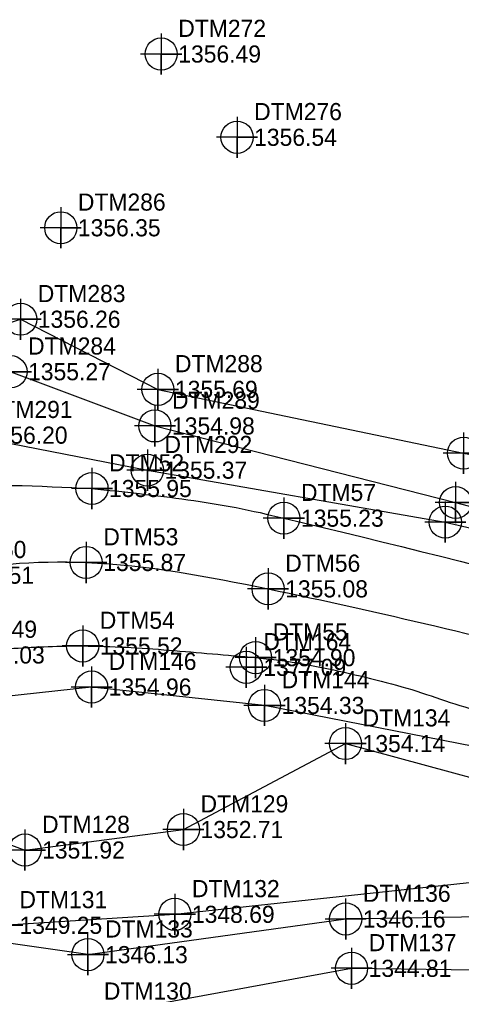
# Model space of a CAD drawing. Extents: x 1251905 to 1252853, y 859795 to 860170.
# Drawn here: x 1252087.6 to 1252152.2, y 860021.6 to 860163.9 of the extents above; entities that cross this region are included whole.
import ezdxf

# ---------------------------------------------------------------- set-up
doc = ezdxf.new("R2010")
doc.units = 0
for name, color, linetype in [('Exist DTM Breakline', 7, 'Continuous'), ('Exist DTM Breakline Cogo Elevation', 7, 'Continuous'), ('Exist DTM Breakline Cogo Number', 7, 'Continuous'), ('Exist DTM Breakline Cogo Point CELL', 7, 'Continuous'), ('Exist DTM Breakline Underwater', 7, 'Continuous'), ('Exist DTM Breakline Underwater Cogo Elevation', 7, 'Continuous'), ('Exist DTM Breakline Underwater Cogo Number', 7, 'Continuous'), ('Exist DTM Breakline Underwater Cogo Point CELL', 7, 'Continuous'), ('Exist DTM Crownline', 7, 'Continuous'), ('Exist DTM Crownline Cogo Elevation', 7, 'Continuous'), ('Exist DTM Crownline Cogo Number', 7, 'Continuous'), ('Exist DTM Crownline Cogo Point CELL', 7, 'Continuous'), ('Exist DTM Regular Point CELL', 7, 'Continuous'), ('Exist DTM Regular Point Cogo Elevation', 7, 'Continuous'), ('Exist DTM Regular Point Cogo Number', 7, 'Continuous'), ('Exist Hydro Stream or Body of Water', 7, 'Continuous'), ('Exist Hydro Stream or Body of Water Cogo Elevation', 7, 'Continuous'), ('Exist Hydro Stream or Body of Water Cogo Number', 7, 'Continuous'), ('Exist Hydro Stream or Body of Water Cogo Point CELL', 7, 'Continuous'), ('Exist Roads EOP', 7, 'Continuous'), ('Exist Roads EOP Cogo Elevation', 7, 'Continuous'), ('Exist Roads EOP Cogo Number', 7, 'Continuous'), ('Exist Roads EOP Cogo Point CELL', 7, 'Continuous'), ('Exist Utilities Power UG Cable Cogo Elevation', 7, 'Continuous'), ('Exist Utilities Power UG Cable Cogo Number', 7, 'Continuous'), ('Exist Utilities Power UG Cable Cogo Point CELL', 7, 'Continuous'), ('Exist Vegetation Tree Cogo Elevation', 7, 'Continuous'), ('Exist Vegetation Tree Cogo Number', 7, 'Continuous')]:
    doc.layers.add(name, color=color, linetype=linetype)

msp = doc.modelspace()

# ---------------------------------------------------------------- linework, layer by layer
at = {"layer": 'Exist DTM Breakline'}
for points in [[(1251958.1300000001, 860094.898), (1251998.718, 860091.9280000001), (1252030.771, 860103.262), (1252049.551, 860107.507), (1252087.7920000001, 860120.138), (1252107.828, 860109.909), (1252152.49, 860100.596), (1252183.064, 860094.812), (1252211.5150000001, 860083.799), (1252212.351, 860093.22), (1252191.02, 860107.9450000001), (1252193.563, 860139.71)], [(1252049.493, 860105.996), (1252086.378, 860112.482), (1252107.399, 860104.568), (1252151.324, 860093.395), (1252178.994, 860086.087), (1252207.96, 860079.566), (1252223.7380000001, 860077.321)], [(1252042.065, 860097.328), (1252080.061, 860103.224), (1252106.299, 860098.116), (1252149.813, 860090.533), (1252176.834, 860084.313), (1252221.078, 860071.872)], [(1252212.143, 860042.894), (1252165.922, 860055.456), (1252123.408, 860063.782), (1252098.156, 860066.464), (1252072.182, 860063.615), (1252055.654, 860055.275)], [(1252061.299, 860052.806), (1252088.425, 860042.6780000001), (1252111.564, 860045.6680000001), (1252135.233, 860058.213), (1252169.648, 860048.881), (1252211.681, 860040.318)], [(1252046.935, 860042.529), (1252048.558, 860037.478), (1252071.192, 860034.305), (1252085.116, 860031.692), (1252110.305, 860033.296), (1252166.428, 860039.344), (1252210.773, 860033.4230000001)]]:
    msp.add_lwpolyline(points, dxfattribs=at)
at = {"layer": 'Exist DTM Breakline Cogo Point CELL'}
for points in [[(1252087.7920000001, 860123.1379999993), (1252087.7920000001, 860117.1379999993), (1252087.7920000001, 860120.1379999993), (1252090.7920000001, 860120.1379999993), (1252084.7920000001, 860120.1379999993)], [(1252086.378, 860115.4819999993), (1252086.378, 860109.4819999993), (1252086.378, 860112.4819999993), (1252089.378, 860112.4819999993), (1252083.378, 860112.4819999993)], [(1252107.828, 860112.9089999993), (1252107.828, 860106.9089999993), (1252107.828, 860109.9089999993), (1252110.828, 860109.9089999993), (1252104.828, 860109.9089999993)], [(1252107.399, 860107.5679999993), (1252107.399, 860101.5679999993), (1252107.399, 860104.5679999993), (1252110.399, 860104.5679999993), (1252104.399, 860104.5679999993)], [(1252152.49, 860103.5959999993), (1252152.49, 860097.5959999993), (1252152.49, 860100.5959999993), (1252155.49, 860100.5959999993), (1252149.49, 860100.5959999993)], [(1252106.299, 860101.1159999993), (1252106.299, 860095.1159999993), (1252106.299, 860098.1159999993), (1252109.299, 860098.1159999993), (1252103.299, 860098.1159999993)], [(1252151.324, 860096.3949999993), (1252151.324, 860090.3949999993), (1252151.324, 860093.3949999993), (1252154.324, 860093.3949999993), (1252148.324, 860093.3949999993)], [(1252149.813, 860093.5329999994), (1252149.813, 860087.5329999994), (1252149.813, 860090.5329999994), (1252152.813, 860090.5329999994), (1252146.813, 860090.5329999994)], [(1252098.156, 860069.4639999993), (1252098.156, 860063.4639999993), (1252098.156, 860066.4639999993), (1252101.156, 860066.4639999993), (1252095.156, 860066.4639999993)], [(1252123.408, 860066.7819999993), (1252123.408, 860060.7819999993), (1252123.408, 860063.7819999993), (1252126.408, 860063.7819999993), (1252120.408, 860063.7819999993)], [(1252135.233, 860061.2129999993), (1252135.233, 860055.2129999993), (1252135.233, 860058.2129999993), (1252138.233, 860058.2129999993), (1252132.233, 860058.2129999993)], [(1252111.564, 860048.6679999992), (1252111.564, 860042.6679999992), (1252111.564, 860045.6679999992), (1252114.564, 860045.6679999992), (1252108.564, 860045.6679999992)], [(1252088.425, 860045.6779999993), (1252088.425, 860039.6779999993), (1252088.425, 860042.6779999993), (1252091.425, 860042.6779999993), (1252085.425, 860042.6779999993)], [(1252110.305, 860036.2959999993), (1252110.305, 860030.2959999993), (1252110.305, 860033.2959999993), (1252113.305, 860033.2959999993), (1252107.305, 860033.2959999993)], [(1252085.116, 860034.6919999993), (1252085.116, 860028.6919999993), (1252085.116, 860031.6919999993), (1252088.116, 860031.6919999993), (1252082.116, 860031.6919999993)]]:
    msp.add_lwpolyline(points, dxfattribs=at)
for centre in [(1252087.7920000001, 860120.1379999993), (1252086.378, 860112.4819999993), (1252107.828, 860109.9089999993), (1252107.399, 860104.5679999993), (1252152.49, 860100.5959999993), (1252106.299, 860098.1159999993), (1252151.324, 860093.3949999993), (1252149.813, 860090.5329999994), (1252098.156, 860066.4639999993), (1252123.408, 860063.7819999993), (1252135.233, 860058.2129999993), (1252111.564, 860045.6679999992), (1252088.425, 860042.6779999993), (1252110.305, 860033.2959999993)]:
    msp.add_circle(centre, 2.344041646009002, dxfattribs=at)
at = {"layer": 'Exist DTM Breakline Underwater'}
msp.add_lwpolyline([(1251927.42, 860049.6630000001), (1251960.607, 860043.4280000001), (1251991.544, 860038.5430000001), (1252023.095, 860021.002), (1252051.108, 860015.006), (1252097.4440000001, 860018.35), (1252136.124, 860025.415), (1252179.795, 860024.836), (1252209.0420000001, 860015.729)], dxfattribs=at)
at = {"layer": 'Exist DTM Breakline Underwater Cogo Point CELL'}
msp.add_lwpolyline([(1252136.124, 860028.4149999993), (1252136.124, 860022.4149999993), (1252136.124, 860025.4149999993), (1252139.124, 860025.4149999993), (1252133.124, 860025.4149999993)], dxfattribs=at)
msp.add_circle((1252136.124, 860025.4149999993), 2.344041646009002, dxfattribs=at)
at = {"layer": 'Exist DTM Crownline'}
msp.add_spline([(1252036.243, 860048.539), (1252039.0760000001, 860060.231), (1252047.752, 860070.723), (1252058.446, 860077.2170000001), (1252075.17, 860082.787), (1252097.364, 860084.644), (1252123.933, 860080.792), (1252172.517, 860069.427), (1252214.359, 860058.511)], degree=3, dxfattribs=at)
at = {"layer": 'Exist DTM Crownline Cogo Point CELL'}
for points in [[(1252097.364, 860087.6439999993), (1252097.364, 860081.6439999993), (1252097.364, 860084.6439999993), (1252100.364, 860084.6439999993), (1252094.364, 860084.6439999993)], [(1252123.933, 860083.7919999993), (1252123.933, 860077.7919999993), (1252123.933, 860080.7919999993), (1252126.933, 860080.7919999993), (1252120.933, 860080.7919999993)]]:
    msp.add_lwpolyline(points, dxfattribs=at)
for centre in [(1252097.364, 860084.6439999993), (1252123.933, 860080.7919999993)]:
    msp.add_circle(centre, 2.344041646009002, dxfattribs=at)
at = {"layer": 'Exist DTM Regular Point CELL'}
for points in [[(1252108.312, 860161.8449999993), (1252108.312, 860155.8449999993), (1252108.312, 860158.8449999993), (1252111.312, 860158.8449999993), (1252105.312, 860158.8449999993)], [(1252119.394, 860149.6939999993), (1252119.394, 860143.6939999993), (1252119.394, 860146.6939999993), (1252122.394, 860146.6939999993), (1252116.394, 860146.6939999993)], [(1252093.6500000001, 860136.4879999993), (1252093.6500000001, 860130.4879999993), (1252093.6500000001, 860133.4879999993), (1252096.6500000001, 860133.4879999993), (1252090.6500000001, 860133.4879999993)]]:
    msp.add_lwpolyline(points, dxfattribs=at)
for centre in [(1252108.312, 860158.8449999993), (1252119.394, 860146.6939999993), (1252093.6500000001, 860133.4879999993)]:
    msp.add_circle(centre, 2.344041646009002, dxfattribs=at)
at = {"layer": 'Exist Hydro Stream or Body of Water'}
for points in [[(1252097.617, 860027.4109999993), (1252046.52, 860034.7289999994)], [(1252097.617, 860027.411), (1252135.268, 860032.617), (1252180.354, 860033.405), (1252216.928, 860028.966)]]:
    msp.add_lwpolyline(points, dxfattribs=at)
at = {"layer": 'Exist Hydro Stream or Body of Water Cogo Point CELL'}
for points in [[(1252132.268, 860032.6169999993), (1252138.268, 860032.6169999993), (1252135.268, 860032.6169999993), (1252135.268, 860029.6169999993), (1252135.268, 860035.6169999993)], [(1252094.617, 860027.4109999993), (1252100.617, 860027.4109999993), (1252097.617, 860027.4109999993), (1252097.617, 860024.4109999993), (1252097.617, 860030.4109999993)]]:
    msp.add_lwpolyline(points, dxfattribs=at)
for centre in [(1252135.268, 860032.6169999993), (1252097.617, 860027.4109999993)]:
    msp.add_circle(centre, 2.344041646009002, dxfattribs=at)
at = {"layer": 'Exist Roads EOP'}
for points in [[(1252051.592, 860092.3719999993), (1252074.9292293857, 860095.6794298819), (1252098.205, 860095.4409999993)], [(1252098.205, 860095.441), (1252105.1614077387, 860094.6882099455), (1252112.220556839, 860093.7969971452), (1252119.2789275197, 860092.6450357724), (1252126.233, 860091.11), (1252217.458, 860067.633)], [(1252045.803, 860048.12), (1252049.087, 860055.674), (1252050.2153975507, 860057.6515921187), (1252051.6839917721, 860059.4129647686), (1252053.3720901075, 860061.0363550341), (1252055.159, 860062.6), (1252057.0142268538, 860064.1325732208), (1252058.9250323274, 860065.5135143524), (1252060.9378216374, 860066.7191983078), (1252063.099, 860067.726), (1252069.836107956, 860069.8939456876), (1252076.731, 860071.145), (1252086.7906137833, 860072.1203664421), (1252096.85, 860072.458), (1252103.1642067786, 860072.2657761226), (1252109.4781924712, 860071.8459595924), (1252115.7920819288, 860071.306163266), (1252122.106, 860070.7540000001), (1252128.211654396, 860069.9862457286), (1252134.2921622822, 860068.7856334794), (1252146.3586576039, 860065.6279820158), (1252158.2673241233, 860062.3653395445), (1252164.150546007, 860061.0334885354), (1252169.98, 860060.082), (1252169.9800000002, 860060.082)]]:
    msp.add_spline(points, degree=3, dxfattribs=at)
at = {"layer": 'Exist Roads EOP Cogo Point CELL'}
for points in [[(1252098.205, 860098.4409999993), (1252098.205, 860092.4409999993), (1252098.205, 860095.4409999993), (1252101.205, 860095.4409999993), (1252095.205, 860095.4409999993)], [(1252126.233, 860094.1099999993), (1252126.233, 860088.1099999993), (1252126.233, 860091.1099999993), (1252129.233, 860091.1099999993), (1252123.233, 860091.1099999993)], [(1252096.85, 860075.4579999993), (1252096.85, 860069.4579999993), (1252096.85, 860072.4579999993), (1252099.85, 860072.4579999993), (1252093.85, 860072.4579999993)], [(1252122.106, 860073.7539999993), (1252122.106, 860067.7539999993), (1252122.106, 860070.7539999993), (1252125.106, 860070.7539999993), (1252119.106, 860070.7539999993)]]:
    msp.add_lwpolyline(points, dxfattribs=at)
for centre in [(1252098.205, 860095.4409999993), (1252126.233, 860091.1099999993), (1252096.85, 860072.4579999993), (1252122.106, 860070.7539999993)]:
    msp.add_circle(centre, 2.344041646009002, dxfattribs=at)
at = {"layer": 'Exist Utilities Power UG Cable Cogo Point CELL'}
msp.add_lwpolyline([(1252120.746, 860072.3399999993), (1252120.746, 860066.3399999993), (1252120.746, 860069.3399999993), (1252123.746, 860069.3399999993), (1252117.746, 860069.3399999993)], dxfattribs=at)
msp.add_circle((1252120.746, 860069.3399999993), 2.344041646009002, dxfattribs=at)

# ---------------------------------------------------------------- texts
at = {"layer": 'Exist DTM Breakline Cogo Elevation'}
for s, p in [('1356.26', (1252090.2920000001, 860118.888)), ('1355.27', (1252088.878, 860111.232)), ('1355.69', (1252110.328, 860108.659)), ('1354.98', (1252109.899, 860103.318)), ('1356.20', (1252082.561, 860101.974)), ('1355.37', (1252108.799, 860096.866)), ('1354.96', (1252100.656, 860065.214)), ('1354.33', (1252125.908, 860062.532)), ('1354.14', (1252137.733, 860056.963)), ('1352.71', (1252114.064, 860044.4180000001)), ('1351.92', (1252090.925, 860041.4280000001)), ('1348.69', (1252112.805, 860032.046)), ('1349.25', (1252087.616, 860030.442))]:
    msp.add_text(s, height=2.5, dxfattribs=at).set_placement(p)
at = {"layer": 'Exist DTM Breakline Cogo Number'}
for s, p in [('DTM283', (1252090.2920000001, 860122.638)), ('DTM284', (1252088.878, 860114.982)), ('DTM288', (1252110.328, 860112.409)), ('DTM289', (1252109.899, 860107.068)), ('DTM291', (1252082.561, 860105.724)), ('DTM292', (1252108.799, 860100.616)), ('DTM146', (1252100.656, 860068.964)), ('DTM144', (1252125.908, 860066.282)), ('DTM134', (1252137.733, 860060.713)), ('DTM129', (1252114.064, 860048.1680000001)), ('DTM128', (1252090.925, 860045.1780000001)), ('DTM132', (1252112.805, 860035.796)), ('DTM131', (1252087.616, 860034.192))]:
    msp.add_text(s, height=2.5, dxfattribs=at).set_placement(p)
at = {"layer": 'Exist DTM Breakline Underwater Cogo Elevation'}
msp.add_text('1344.81', height=2.5, dxfattribs=at).set_placement((1252138.624, 860024.165))
at = {"layer": 'Exist DTM Breakline Underwater Cogo Number'}
for s, p in [('DTM137', (1252138.624, 860027.915)), ('DTM130', (1252099.9440000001, 860020.85))]:
    msp.add_text(s, height=2.5, dxfattribs=at).set_placement(p)
at = {"layer": 'Exist DTM Crownline Cogo Elevation'}
for s, p in [('1355.87', (1252099.864, 860083.394)), ('1356.51', (1252077.67, 860081.537)), ('1355.08', (1252126.433, 860079.542))]:
    msp.add_text(s, height=2.5, dxfattribs=at).set_placement(p)
at = {"layer": 'Exist DTM Crownline Cogo Number'}
for s, p in [('DTM53', (1252099.864, 860087.144)), ('DTM50', (1252077.67, 860085.287)), ('DTM56', (1252126.433, 860083.292))]:
    msp.add_text(s, height=2.5, dxfattribs=at).set_placement(p)
at = {"layer": 'Exist DTM Regular Point Cogo Elevation'}
for s, p in [('1356.49', (1252110.812, 860157.595)), ('1356.35', (1252096.1500000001, 860132.238))]:
    msp.add_text(s, height=2.5, dxfattribs=at).set_placement(p)
at = {"layer": 'Exist DTM Regular Point Cogo Number'}
for s, p in [('DTM272', (1252110.812, 860161.345)), ('DTM286', (1252096.1500000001, 860135.988))]:
    msp.add_text(s, height=2.5, dxfattribs=at).set_placement(p)
at = {"layer": 'Exist Hydro Stream or Body of Water Cogo Elevation'}
for s, p in [('1346.16', (1252137.768, 860031.367)), ('1346.13', (1252100.117, 860026.161))]:
    msp.add_text(s, height=2.5, dxfattribs=at).set_placement(p)
at = {"layer": 'Exist Hydro Stream or Body of Water Cogo Number'}
for s, p in [('DTM136', (1252137.768, 860035.117)), ('DTM133', (1252100.117, 860029.911))]:
    msp.add_text(s, height=2.5, dxfattribs=at).set_placement(p)
at = {"layer": 'Exist Roads EOP Cogo Elevation'}
for s, p in [('1355.95', (1252100.705, 860094.191)), ('1355.23', (1252128.733, 860089.86)), ('1355.52', (1252099.35, 860071.208)), ('1356.03', (1252079.231, 860069.895)), ('1354.90', (1252124.606, 860069.5040000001))]:
    msp.add_text(s, height=2.5, dxfattribs=at).set_placement(p)
at = {"layer": 'Exist Roads EOP Cogo Number'}
for s, p in [('DTM52', (1252100.705, 860097.941)), ('DTM57', (1252128.733, 860093.61)), ('DTM54', (1252099.35, 860074.958)), ('DTM49', (1252079.231, 860073.645)), ('DTM55', (1252124.606, 860073.2540000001))]:
    msp.add_text(s, height=2.5, dxfattribs=at).set_placement(p)
at = {"layer": 'Exist Utilities Power UG Cable Cogo Elevation'}
msp.add_text('1377.09', height=2.5, dxfattribs=at).set_placement((1252123.246, 860068.09))
at = {"layer": 'Exist Utilities Power UG Cable Cogo Number'}
msp.add_text('DTM164', height=2.5, dxfattribs=at).set_placement((1252123.246, 860071.84))
at = {"layer": 'Exist Vegetation Tree Cogo Elevation'}
msp.add_text('1356.54', height=2.5, dxfattribs=at).set_placement((1252121.894, 860145.444))
at = {"layer": 'Exist Vegetation Tree Cogo Number'}
msp.add_text('DTM276', height=2.5, dxfattribs=at).set_placement((1252121.894, 860149.194))

doc.saveas('drawing.dxf')
